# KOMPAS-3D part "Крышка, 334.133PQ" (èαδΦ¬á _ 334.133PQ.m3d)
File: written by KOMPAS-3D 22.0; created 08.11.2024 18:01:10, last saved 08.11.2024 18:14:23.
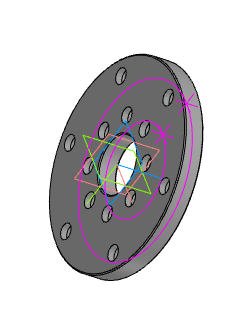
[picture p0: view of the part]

Document properties: Автор: aleksander.larionov.10@gmail.com; Полное имя файла: C:\Мои папки\Работа\Крышки, фланцы\334.133PQ\Крышка _ 334.133PQ.m3d

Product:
- Part/product: Крышка  | designation 334.133PQ
    Материал: Сталь 45 ГОСТ 1050-2013 (density 7810 kg/m3)
    Масса: 2.782462

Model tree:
1. Эскиз:1
2. Элемент выдавливания:1
     Расстояние 1 = 18
3. Эскиз:2  (with: Элемент выдавливания:1)
4. Отверстие:1
     Глубина выреза = 18; Диаметр отверстия = 14; Угол конуса дна = 118; Расстояние 1 = 75; Диаметр цековки = 20; Глубина цековки = 12
5. Массив по концентрической сетке:1  (with: Отверстие:1)  (6 pattern instances)
     Шаг 2 = 360
6. Отверстие:2  (with: Элемент выдавливания:1)
     Глубина выреза = 18; Диаметр отверстия = 14; Угол конуса дна = 118; Расстояние 1 = 40; Диаметр цековки = 20; Глубина цековки = 12
7. Массив по концентрической сетке:2  (with: Отверстие:2)  (8 pattern instances)
     Шаг 2 = 360
8. Фаска:1  (with: Элемент выдавливания:1)  (labels: Сталь 45 ГОСТ 1050-2013)
     Угол = 45; Длина 1 = 1; Длина 2 = 1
